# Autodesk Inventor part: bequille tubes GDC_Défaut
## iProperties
Shininess: 64.0
Length Units: 11269
Angle Units: 11279
Time Units: 11290
Mass Units: 11283
Length Display Precision: 3
Angle Display Precision: 2
Compacted: True
Part Number: bequille tubes GDC_Défaut
Document SubType Name: Modeling
Created: 2006-01
Material: Par défaut
Designer: Fricot
Density: 0.0
Volumn: 0.0
Area: 0.0
PropertySet Name: Model Information
Control State: 0
Master: False
Checked Out: False
Author: Fricot
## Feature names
1. Base1
